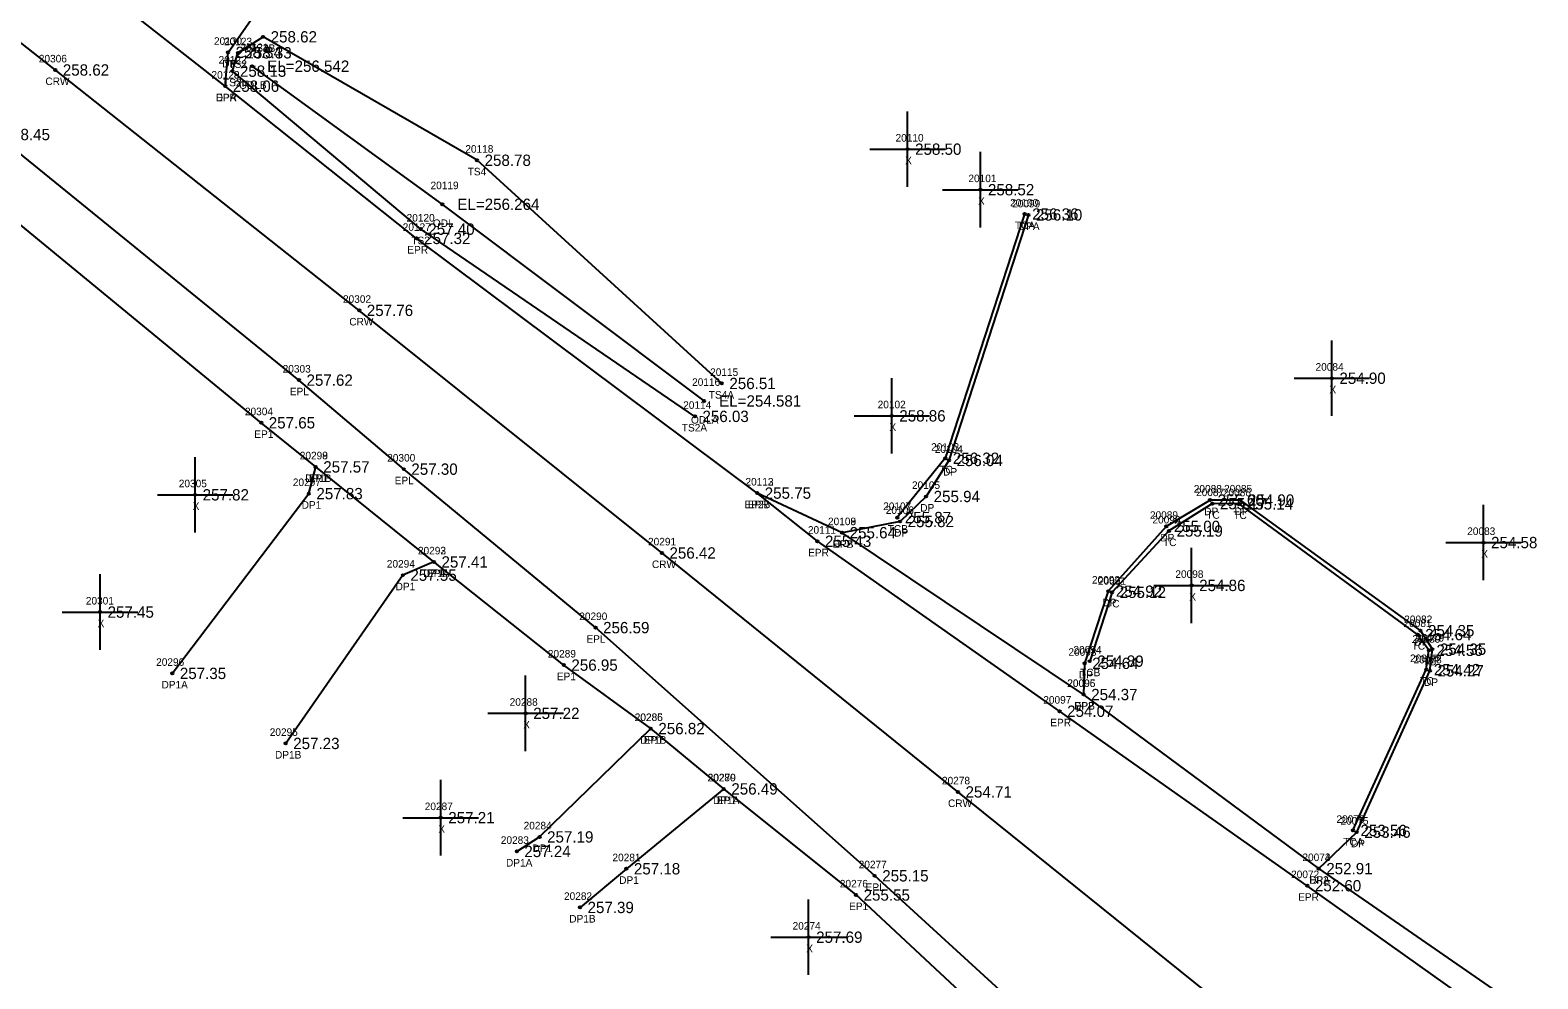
# Model space of a CAD drawing. Extents: x 1961330 to 1962287, y 800294 to 801079.
# Drawn here: x 1961887.6 to 1962087.3, y 800505.6 to 800631.3 of the extents above; entities that cross this region are included whole.
import ezdxf

# ---------------------------------------------------------------- set-up
doc = ezdxf.new("R2010")
doc.units = 0
for name, color, linetype in [('RD_DTM_BkLn1', 7, 'Continuous'), ('RD_DTM_BkLn2', 7, 'Continuous'), ('RD_DTM_BkLn_txCode', 7, 'Continuous'), ('RD_EX_Conc_txCode', 7, 'Continuous'), ('RD_EX_Driveway', 7, 'Continuous'), ('RD_EX_Driveway_txCode', 7, 'Continuous'), ('RD_EX_H2O', 7, 'Continuous'), ('RD_EX_H2O_txCode', 7, 'Continuous'), ('RD_EX_Misc', 7, 'Continuous'), ('RD_EX_Misc_txCode', 7, 'Continuous'), ('RD_EX_Road', 7, 'Continuous'), ('RD_EX_Road_txCode', 7, 'Continuous'), ('RD_EX_TX_Conc_ELEV', 7, 'Continuous'), ('RD_EX_TX_Driveway_ELEV', 7, 'Continuous'), ('RD_EX_TX_H2O_ELEV', 7, 'Continuous'), ('RD_EX_TX_Misc_ELEV', 7, 'Continuous'), ('RD_EX_TX_Road_ELEV', 7, 'Continuous'), ('RD_HC_Survey_ELEV', 7, 'Continuous'), ('RD_HC_Survey_txCode', 7, 'Continuous'), ('RD_SMD_Locator', 7, 'Continuous')]:
    doc.layers.add(name, color=color, linetype=linetype)

msp = doc.modelspace()

# ---------------------------------------------------------------- linework, layer by layer
at = {"layer": 'RD_DTM_BkLn1'}
msp.add_lwpolyline([(1962257.08, 800334.72), (1962203.79, 800372.43), (1962164.31, 800399.58), (1962126.58, 800429.85), (1962084.5, 800463.37), (1962045.12, 800502.48), (1962010.49, 800530.36), (1961971.27, 800562.01), (1961931.18, 800594.14), (1961890.91, 800625.98), (1961844.41, 800662.62), (1961808.07, 800691.13), (1961729.11, 800753.37), (1961696.19, 800780.32), (1961667.25, 800802.66), (1961624.93, 800836.78), (1961588.01, 800866), (1961545.37, 800899.49), (1961472.25, 800957.29), (1961437.91, 800983.99), (1961399.03, 801013.16), (1961365.01, 801035.89)], dxfattribs=at)
at = {"layer": 'RD_DTM_BkLn2'}
for points in [[(1961975.64, 800580.1), (1961939.33, 800604.9), (1961914.37, 800625.82), (1961915.09, 800628.25), (1961918.44, 800630.37)], [(1961979.21, 800584.46), (1961946.78, 800614.02), (1961918.44, 800630.37)], [(1962019.32, 800606.9), (1962008.81, 800574.55), (1962002.45, 800566.7)], [(1962062.81, 800525.26), (1962072.53, 800546.56), (1962072.87, 800549.12), (1962071.38, 800551.2), (1962047.76, 800568.51), (1962044.19, 800568.54), (1962038.44, 800564.92), (1962030.91, 800556.8), (1962027.95, 800547.68)]]:
    msp.add_lwpolyline(points, dxfattribs=at)
at = {"layer": 'RD_EX_Driveway'}
for points in [[(1961913.43, 800623.83), (1961913.8, 800628.31), (1961921.55, 800639.44), (1961911.62, 800648.22), (1961904.99, 800639.52), (1961897.73, 800636.17)], [(1962019.82, 800606.78), (1962009.3, 800574.26), (1962006.27, 800569.49), (1962002.82, 800566.18), (1961995.14, 800564.69)], [(1961906.41, 800546.06), (1961924.5, 800569.87), (1961925.41, 800573.41)], [(1962058.28, 800520.2), (1962063.32, 800525.03), (1962073.01, 800546.4), (1962073.33, 800549.27), (1962071.76, 800551.72), (1962047.9, 800569.02), (1962043.89, 800569.01), (1962038.08, 800565.53), (1962030.4, 800556.95), (1962027.27, 800547.39), (1962027.14, 800543.26)], [(1961941.07, 800560.82), (1961936.95, 800559.07), (1961921.43, 800536.78)], [(1961952.05, 800522.48), (1961955.06, 800524.4), (1961969.8, 800538.75)], [(1961979.47, 800530.76), (1961966.56, 800520.18), (1961960.42, 800515.06)]]:
    msp.add_lwpolyline(points, dxfattribs=at)
at = {"layer": 'RD_EX_H2O'}
msp.add_lwpolyline([(1961976.85, 800582.14), (1961942.17, 800608.19), (1961916.98, 800626.48)], dxfattribs=at)
at = {"layer": 'RD_EX_Misc'}
for p, q in [((1962003.81, 800610.49), (1962003.81, 800620.49)), ((1961998.81, 800615.49), (1962008.81, 800615.49)), ((1962013.46, 800605.12), (1962013.46, 800615.12)), ((1962008.46, 800610.12), (1962018.46, 800610.12)), ((1962060.02, 800580.15), (1962060.02, 800590.15)), ((1962001.72, 800575.17), (1962001.72, 800585.17)), ((1962055.02, 800585.15), (1962065.02, 800585.15)), ((1961996.72, 800580.17), (1962006.72, 800580.17)), ((1961909.43, 800564.71), (1961909.43, 800574.71)), ((1961904.43, 800569.71), (1961914.43, 800569.71)), ((1962080.11, 800558.39), (1962080.11, 800568.39)), ((1962075.11, 800563.39), (1962085.11, 800563.39)), ((1962041.44, 800552.71), (1962041.44, 800562.71)), ((1961896.84, 800549.18), (1961896.84, 800559.18)), ((1962036.44, 800557.71), (1962046.44, 800557.71)), ((1961891.84, 800554.18), (1961901.84, 800554.18)), ((1961953.22, 800535.77), (1961953.22, 800545.77)), ((1961948.22, 800540.77), (1961958.22, 800540.77)), ((1961941.97, 800521.95), (1961941.97, 800531.95)), ((1961936.97, 800526.95), (1961946.97, 800526.95)), ((1961990.7, 800506.12), (1961990.7, 800516.12)), ((1961985.7, 800511.12), (1961995.7, 800511.12))]:
    msp.add_line(p, q, dxfattribs=at)
at = {"layer": 'RD_EX_Road'}
for points in [[(1962276.74, 800366.53), (1962275.76, 800367.28), (1962226.46, 800400.66), (1962183.05, 800429.73), (1962145.98, 800455.38), (1962104.4, 800484.06), (1962056.77, 800517.94), (1962023.95, 800541.05), (1961991.87, 800563.56), (1961983.89, 800569.94), (1961938.77, 800603.67), (1961913.43, 800623.83), (1961897.73, 800636.17), (1961851.62, 800671.61), (1961815.86, 800699.48), (1961795.77, 800715.49), (1961771.88, 800733.73), (1961750.77, 800750.96), (1961735.63, 800762.82), (1961702.92, 800788.52), (1961676.16, 800810.27), (1961651.45, 800830.73), (1961641.14, 800839.02)], [(1962241.79, 800315.68), (1962238.35, 800317.6), (1962189.92, 800352.69), (1962151.64, 800383.49), (1962113.78, 800416.39), (1962074.11, 800451.29), (1962034.78, 800486.96), (1962017.07, 800503.17), (1961999.46, 800519.25), (1961962.48, 800552.12), (1961937.08, 800573.11), (1961923.19, 800584.9), (1961883.07, 800617.43), (1961838.29, 800653.43), (1961801.42, 800682.57), (1961728.41, 800740.86), (1961722.95, 800745.11), (1961689.13, 800771.93), (1961670.14, 800787.03), (1961660.52, 800795.31), (1961637.49, 800813.67)], [(1961992.53, 800418.34), (1962000.94, 800437), (1962011.01, 800464.81), (1962016.84, 800481.64), (1962015.31, 800499.65), (1961996.99, 800516.71), (1961979.47, 800530.76), (1961969.8, 800538.75), (1961958.28, 800547.16), (1961941.07, 800560.82), (1961925.41, 800573.41), (1961918.19, 800579.25), (1961879.32, 800611.18), (1961866.07, 800621.08), (1961838.29, 800653.43)], [(1962275.76, 800367.28), (1962274.03, 800371.18), (1962275.17, 800373.82), (1962239.93, 800394.94), (1962227.76, 800403.12), (1962207.73, 800416.44), (1962184.45, 800431.68), (1962152.89, 800453.77), (1962107.43, 800485.96), (1962091.52, 800497.24), (1962058.28, 800520.2), (1962027.14, 800543.26), (1961995.14, 800564.69), (1961983.89, 800569.94)]]:
    msp.add_lwpolyline(points, dxfattribs=at)
at = {"layer": 'RD_SMD_Locator'}
for centre in [(1961918.44, 800630.37), (1961918.44, 800630.37), (1961913.8, 800628.31), (1961915.09, 800628.25), (1961890.91, 800625.98), (1961914.37, 800625.82), (1961916.98, 800626.48), (1961913.43, 800623.83), (1961913.43, 800623.83), (1962003.81, 800615.49), (1961946.78, 800614.02), (1962013.46, 800610.12), (1961942.17, 800608.19), (1962019.32, 800606.9), (1962019.82, 800606.78), (1961939.33, 800604.9), (1961938.77, 800603.67), (1961931.18, 800594.14), (1961923.19, 800584.9), (1962060.02, 800585.15), (1961979.21, 800584.46), (1961976.85, 800582.14), (1961918.19, 800579.25), (1961975.64, 800580.1), (1962001.72, 800580.17), (1961925.41, 800573.41), (1961925.41, 800573.41), (1961937.08, 800573.11), (1962008.81, 800574.55), (1962009.3, 800574.26), (1961909.43, 800569.71), (1961924.5, 800569.87), (1961983.89, 800569.94), (1961983.89, 800569.94), (1962006.27, 800569.49), (1962043.89, 800569.01), (1962047.9, 800569.02), (1962044.19, 800568.54), (1962047.76, 800568.51), (1962002.45, 800566.7), (1962002.82, 800566.18), (1962038.08, 800565.53), (1962038.44, 800564.92), (1961991.87, 800563.56), (1961995.14, 800564.69), (1961995.14, 800564.69), (1962080.11, 800563.39), (1961941.07, 800560.82), (1961941.07, 800560.82), (1961971.27, 800562.01), (1961936.95, 800559.07), (1962030.4, 800556.95), (1962030.91, 800556.8), (1962041.44, 800557.71), (1961896.84, 800554.18), (1961962.48, 800552.12), (1962071.38, 800551.2), (1962071.76, 800551.72), (1962072.87, 800549.12), (1962073.33, 800549.27), (1961958.28, 800547.16), (1962027.27, 800547.39), (1962027.95, 800547.68), (1961906.41, 800546.06), (1962072.53, 800546.56), (1962073.01, 800546.4), (1962027.14, 800543.26), (1962027.14, 800543.26), (1961953.22, 800540.77), (1962023.95, 800541.05), (1961921.43, 800536.78), (1961969.8, 800538.75), (1961969.8, 800538.75), (1961979.47, 800530.76), (1961979.47, 800530.76), (1962010.49, 800530.36), (1961941.97, 800526.95), (1962062.81, 800525.26), (1962063.32, 800525.03), (1961955.06, 800524.4), (1961952.05, 800522.48), (1961966.56, 800520.18), (1961999.46, 800519.25), (1962058.28, 800520.2), (1962058.28, 800520.2), (1962056.77, 800517.94), (1961960.42, 800515.06), (1961996.99, 800516.71), (1961990.7, 800511.12)]:
    msp.add_circle(centre, 0.15, dxfattribs=at)

# ---------------------------------------------------------------- texts
at = {"layer": 'RD_DTM_BkLn_txCode'}
for s, p in [('20123', (1961913.26, 800629.25)), ('TS2B', (1961916.72, 800628.37)), ('TS4B', (1961916.72, 800628.37)), ('20122', (1961912.54, 800626.82)), ('TS2', (1961913.85, 800626.25)), ('TS2', (1961913.13, 800623.82)), ('20118', (1961945.23, 800615.02)), ('TS4', (1961945.54, 800612.02)), ('20120', (1961937.45, 800605.9)), ('TS2', (1961938.08, 800602.9)), ('20115', (1961977.66, 800585.46)), ('TS4A', (1961977.48, 800582.46)), ('20114', (1961974.09, 800581.1)), ('TS2A', (1961973.91, 800578.1))]:
    msp.add_text(s, height=1, dxfattribs=at).set_placement(p)
at = {"layer": 'RD_EX_Conc_txCode'}
for s, p in [('20100', (1962017.4, 800607.9)), ('TCA', (1962018.03, 800604.9)), ('20103', (1962006.93, 800575.55)), ('TC', (1962008.01, 800572.55)), ('20087', (1962042.03, 800569.54)), ('20086', (1962045.58, 800569.51)), ('20107', (1962000.58, 800567.7)), ('20090', (1962036.25, 800565.92)), ('TC', (1962043.39, 800566.54)), ('TC', (1962046.96, 800566.51)), ('TCB', (1962001.18, 800564.7)), ('TC', (1962037.65, 800562.92)), ('20091', (1962029.03, 800557.8)), ('TC', (1962030.11, 800554.8)), ('20081', (1962069.51, 800552.2)), ('20080', (1962070.67, 800550.12)), ('20094', (1962025.79, 800548.68)), ('TC', (1962070.59, 800549.2)), ('20077', (1962070.37, 800547.56)), ('TC', (1962072.07, 800547.12)), ('TCB', (1962026.68, 800545.68)), ('TC', (1962071.73, 800544.56)), ('20076', (1962060.63, 800526.26)), ('TCA', (1962061.53, 800523.26))]:
    msp.add_text(s, height=1, dxfattribs=at).set_placement(p)
at = {"layer": 'RD_EX_Driveway_txCode'}
for s, p in [('20130', (1961911.93, 800629.31)), ('DP', (1961913.02, 800626.31)), ('20129', (1961911.6, 800624.83)), ('DPA', (1961912.17, 800621.83)), ('20099', (1962017.66, 800607.78)), ('DPA', (1962018.55, 800604.78)), ('20298', (1961923.3, 800574.41)), ('20104', (1962007.42, 800575.26)), ('DP', (1962008.52, 800572.26)), ('20297', (1961922.38, 800570.87)), ('DP1B', (1961924, 800571.41)), ('20105', (1962004.4, 800570.49)), ('20088', (1962041.73, 800570.01)), ('20085', (1962045.74, 800570.02)), ('DP1', (1961923.55, 800567.87)), ('20106', (1962000.92, 800567.18)), ('DP', (1962005.49, 800567.49)), ('20089', (1962035.92, 800566.53)), ('DP', (1962043.11, 800567.01)), ('DP', (1962047.12, 800567.02)), ('20108', (1961993.27, 800565.69)), ('DP', (1962002.04, 800564.18)), ('DPB', (1961993.89, 800562.69)), ('DP', (1962037.3, 800563.53)), ('20294', (1961934.83, 800560.07)), ('20293', (1961938.95, 800561.82)), ('DP1A', (1961939.63, 800558.82)), ('20092', (1962028.24, 800557.95)), ('DP1', (1961936, 800557.07)), ('DP', (1962029.62, 800554.95)), ('20082', (1962069.6, 800552.72)), ('20079', (1962071.18, 800550.27)), ('20093', (1962025.12, 800548.39)), ('DP', (1962070.98, 800549.72)), ('20296', (1961904.27, 800547.06)), ('20078', (1962070.85, 800547.4)), ('DP', (1962072.55, 800547.27)), ('DP1A', (1961904.98, 800544.06)), ('20095', (1962024.98, 800544.26)), ('DP', (1962026.5, 800545.39)), ('DP', (1962072.23, 800544.4)), ('DPB', (1962025.88, 800541.26)), ('20285', (1961967.68, 800539.75)), ('20295', (1961919.32, 800537.78)), ('DP1B', (1961968.38, 800536.75)), ('DP1B', (1961920.02, 800534.78)), ('20280', (1961977.31, 800531.76)), ('DP1A', (1961978.04, 800528.76)), ('20075', (1962061.16, 800526.03)), ('20284', (1961952.95, 800525.4)), ('20283', (1961949.93, 800523.48)), ('DP1', (1961954.12, 800522.4)), ('DP', (1962062.54, 800523.03)), ('DP1A', (1961950.62, 800520.48)), ('20281', (1961964.72, 800521.18)), ('20074', (1962056.12, 800521.2)), ('DP1', (1961965.61, 800518.18)), ('DPA', (1962057.01, 800518.2)), ('20282', (1961958.3, 800516.06)), ('DP1B', (1961959, 800513.06))]:
    msp.add_text(s, height=1, dxfattribs=at).set_placement(p)
at = {"layer": 'RD_EX_H2O_txCode'}
for s, p in [('20121', (1961915.43, 800628.48)), ('ODLB', (1961915.26, 800623.48)), ('20119', (1961940.62, 800610.19)), ('ODL', (1961940.93, 800605.19)), ('20116', (1961975.27, 800584.14)), ('ODLA', (1961975.12, 800579.14))]:
    msp.add_text(s, height=1, dxfattribs=at).set_placement(p)
at = {"layer": 'RD_EX_Misc_txCode'}
for s, p in [('20110', (1962002.22, 800616.49)), ('X', (1962003.49, 800613.49)), ('20101', (1962011.87, 800611.12)), ('X', (1962013.15, 800608.12)), ('20084', (1962057.86, 800586.15)), ('X', (1962059.7, 800583.15)), ('20102', (1961999.85, 800581.17)), ('X', (1962001.41, 800578.17)), ('20305', (1961907.27, 800570.71)), ('X', (1961909.11, 800567.71)), ('20083', (1962077.95, 800564.39)), ('X', (1962079.8, 800561.39)), ('20098', (1962039.29, 800558.71)), ('20301', (1961894.96, 800555.18)), ('X', (1962041.13, 800555.71)), ('X', (1961896.52, 800552.18)), ('20288', (1961951.1, 800541.77)), ('X', (1961952.9, 800538.77)), ('20287', (1961939.85, 800527.95)), ('X', (1961941.65, 800524.95)), ('20274', (1961988.58, 800512.12)), ('X', (1961990.39, 800509.12))]:
    msp.add_text(s, height=1, dxfattribs=at).set_placement(p)
at = {"layer": 'RD_EX_Road_txCode'}
for s, p in [('20128', (1961911.6, 800624.83)), ('EPR', (1961912.2, 800621.83)), ('20127', (1961936.94, 800604.67)), ('EPR', (1961937.54, 800601.67)), ('20303', (1961921.03, 800585.9)), ('EPL', (1961921.98, 800582.9)), ('20304', (1961916.03, 800580.25)), ('EP1', (1961917.27, 800577.25)), ('20299', (1961923.3, 800574.41)), ('20300', (1961934.88, 800574.11)), ('EP1', (1961924.49, 800571.41)), ('EPL', (1961935.87, 800571.11)), ('20112', (1961982.34, 800570.94)), ('20113', (1961982.34, 800570.94)), ('EP2B', (1961982.21, 800567.94)), ('EPR', (1961982.66, 800567.94)), ('20111', (1961990.61, 800564.56)), ('20109', (1961993.27, 800565.69)), ('EP2', (1961993.94, 800562.69)), ('20292', (1961938.95, 800561.82)), ('EPR', (1961990.64, 800561.56)), ('EP1', (1961940.15, 800558.82)), ('20290', (1961960.32, 800553.12)), ('EPL', (1961961.27, 800550.12)), ('20289', (1961956.16, 800548.16)), ('EP1', (1961957.36, 800545.16)), ('20096', (1962024.96, 800544.26)), ('20097', (1962021.79, 800542.05)), ('EP2', (1962025.93, 800541.26)), ('20286', (1961967.66, 800539.75)), ('EPR', (1962022.72, 800539.05)), ('EP1', (1961968.88, 800536.75)), ('20279', (1961977.35, 800531.76)), ('EP1', (1961978.55, 800528.76)), ('20277', (1961997.34, 800520.25)), ('20073', (1962056.12, 800521.2)), ('20072', (1962054.62, 800518.94)), ('EP2', (1962057.07, 800518.2)), ('20276', (1961994.84, 800517.71)), ('EPL', (1961998.26, 800517.25)), ('EP1', (1961996.06, 800514.71)), ('EPR', (1962055.55, 800515.94))]:
    msp.add_text(s, height=1, dxfattribs=at).set_placement(p)
at = {"layer": 'RD_EX_TX_Conc_ELEV'}
for s, p in [('256.36', (1962020.32, 800606.15)), ('256.32', (1962009.81, 800573.8)), ('255.17', (1962045.19, 800567.79)), ('255.14', (1962048.76, 800567.76)), ('255.87', (1962003.45, 800565.95)), ('255.19', (1962039.44, 800564.17)), ('255.12', (1962031.91, 800556.05)), ('254.64', (1962072.38, 800550.45)), ('254.56', (1962073.87, 800548.37)), ('254.89', (1962028.95, 800546.93)), ('254.42', (1962073.53, 800545.81)), ('253.56', (1962063.81, 800524.51))]:
    msp.add_text(s, height=1.5, dxfattribs=at).set_placement(p)
at = {"layer": 'RD_EX_TX_Driveway_ELEV'}
for s, p in [('258.34', (1961914.8, 800627.56)), ('258.06', (1961914.43, 800623.08)), ('256.10', (1962020.82, 800606.03)), ('256.04', (1962010.3, 800573.51)), ('257.57', (1961926.41, 800572.66)), ('257.83', (1961925.5, 800569.12)), ('255.94', (1962007.27, 800568.74)), ('255.00', (1962044.89, 800568.26)), ('254.90', (1962048.9, 800568.27)), ('255.82', (1962003.82, 800565.43)), ('255.64', (1961996.14, 800563.94)), ('255.00', (1962039.08, 800564.78)), ('257.41', (1961942.07, 800560.07)), ('257.55', (1961937.95, 800558.32)), ('254.92', (1962031.4, 800556.2)), ('254.35', (1962072.76, 800550.97)), ('254.35', (1962074.33, 800548.52)), ('254.64', (1962028.27, 800546.64)), ('254.27', (1962074.01, 800545.65)), ('257.35', (1961907.41, 800545.31)), ('254.37', (1962028.14, 800542.51)), ('256.82', (1961970.8, 800538)), ('257.23', (1961922.43, 800536.03)), ('256.49', (1961980.47, 800530.01)), ('257.19', (1961956.06, 800523.65)), ('253.46', (1962064.32, 800524.28)), ('257.24', (1961953.05, 800521.73)), ('257.18', (1961967.56, 800519.43)), ('252.91', (1962059.28, 800519.45)), ('257.39', (1961961.42, 800514.31))]:
    msp.add_text(s, height=1.5, dxfattribs=at).set_placement(p)
at = {"layer": 'RD_EX_TX_H2O_ELEV'}
for s, p in [('EL=256.542', (1961918.98, 800625.73)), ('EL=256.264', (1961944.17, 800607.44)), ('EL=254.581', (1961978.85, 800581.39))]:
    msp.add_text(s, height=1.5, dxfattribs=at).set_placement(p)
at = {"layer": 'RD_EX_TX_Misc_ELEV'}
for s, p in [('258.62', (1961919.44, 800629.62)), ('258.62', (1961919.44, 800629.62)), ('258.33', (1961916.09, 800627.5)), ('258.13', (1961915.37, 800625.07)), ('258.50', (1962004.81, 800614.74)), ('258.78', (1961947.78, 800613.27)), ('258.52', (1962014.46, 800609.37)), ('257.40', (1961940.33, 800604.15)), ('256.51', (1961980.21, 800583.71)), ('254.90', (1962061.02, 800584.4)), ('256.03', (1961976.64, 800579.35)), ('258.86', (1962002.72, 800579.42)), ('257.82', (1961910.43, 800568.96)), ('254.58', (1962081.11, 800562.64)), ('254.86', (1962042.44, 800556.96)), ('257.45', (1961897.84, 800553.43)), ('257.22', (1961954.22, 800540.02)), ('257.21', (1961942.97, 800526.2)), ('257.69', (1961991.7, 800510.37))]:
    msp.add_text(s, height=1.5, dxfattribs=at).set_placement(p)
at = {"layer": 'RD_EX_TX_Road_ELEV'}
for s, p in [('258.06', (1961914.43, 800623.08)), ('258.45', (1961884.07, 800616.68)), ('257.32', (1961939.77, 800602.92)), ('257.62', (1961924.19, 800584.15)), ('257.65', (1961919.19, 800578.5)), ('257.57', (1961926.41, 800572.66)), ('257.30', (1961938.08, 800572.36)), ('255.75', (1961984.89, 800569.19)), ('255.75', (1961984.89, 800569.19)), ('255.64', (1961996.14, 800563.94)), ('255.43', (1961992.87, 800562.81)), ('257.41', (1961942.07, 800560.07)), ('256.59', (1961963.48, 800551.37)), ('256.95', (1961959.28, 800546.41)), ('254.37', (1962028.14, 800542.51)), ('254.07', (1962024.95, 800540.3)), ('256.82', (1961970.8, 800538)), ('256.49', (1961980.47, 800530.01)), ('252.91', (1962059.28, 800519.45)), ('255.15', (1962000.46, 800518.5)), ('255.55', (1961997.99, 800515.96)), ('252.60', (1962057.77, 800517.19))]:
    msp.add_text(s, height=1.5, dxfattribs=at).set_placement(p)
at = {"layer": 'RD_HC_Survey_ELEV'}
for s, p in [('258.62', (1961891.91, 800625.23)), ('257.76', (1961932.18, 800593.39)), ('256.42', (1961972.27, 800561.26)), ('254.71', (1962011.49, 800529.61))]:
    msp.add_text(s, height=1.5, dxfattribs=at).set_placement(p)
at = {"layer": 'RD_HC_Survey_txCode'}
for s, p in [('20306', (1961888.73, 800626.98)), ('CRW', (1961889.6, 800623.98)), ('20302', (1961929.02, 800595.14)), ('CRW', (1961929.86, 800592.14)), ('20291', (1961969.43, 800563.01)), ('CRW', (1961969.95, 800560.01)), ('20278', (1962008.37, 800531.36)), ('CRW', (1962009.17, 800528.36))]:
    msp.add_text(s, height=1, dxfattribs=at).set_placement(p)

doc.saveas('drawing.dxf')
